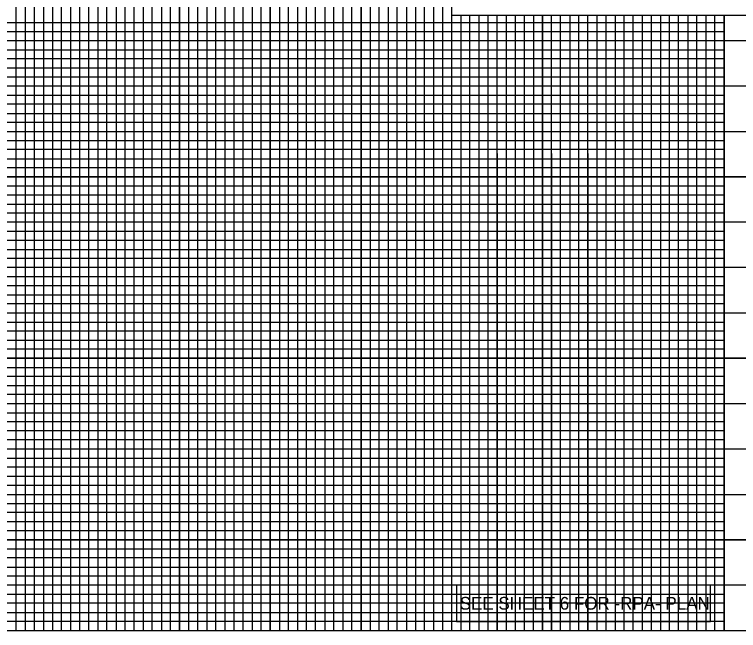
# Model space of a CAD drawing. Extents: x 1648862 to 1650715, y 820691 to 821791.
# Drawn here: x 1650088.3 to 1650487.2, y 821266 to 821605.5 of the extents above; entities that cross this region are included whole.
import ezdxf

# ---------------------------------------------------------------- set-up
doc = ezdxf.new("R2010")
doc.units = 0
for name, color, linetype in [('Prop Dimension', 7, 'Continuous'), ('Prop Grid Mask', 7, 'Continuous'), ('Sheet DOT Grid CELL', 7, 'Continuous'), ('Sheet Layout Profile Border Port 1', 7, 'Continuous'), ('Sheet Profile CELL', 7, 'Continuous'), ('Sheet Profile Grid Major CELL', 7, 'Continuous'), ('Sheet Profile Grid Middle CELL', 7, 'Continuous'), ('Sheet Profile Grid Minor CELL', 7, 'Continuous'), ('Sheet Sticker Exception Certification CELL', 7, 'Continuous')]:
    doc.layers.add(name, color=color, linetype=linetype)

msp = doc.modelspace()

# ---------------------------------------------------------------- linework, layer by layer
at = {"layer": 'Prop Grid Mask'}
msp.add_lwpolyline([(1650331.78, 821291.02), (1650331.78, 821271.02), (1650471.78, 821271.02), (1650471.78, 821291.02)], close=True, dxfattribs=at)
at = {"layer": 'Sheet DOT Grid CELL'}
for p, q in [((1650129.28, 821266.02), (1650129.28, 821718.48)), ((1650179.28, 821266.02), (1650179.28, 821716.02)), ((1650229.28, 821266.02), (1650229.28, 821718.48)), ((1650279.28, 821266.02), (1650279.28, 821718.48)), ((1650329.28, 821266.02), (1650329.28, 821628.47)), ((1650379.28, 821266.02), (1650379.28, 821604.97)), ((1650429.28, 821266.02), (1650429.28, 821604.97)), ((1650479.28, 821266.02), (1650479.28, 821604.97)), ((1650529.28, 821566.02), (1649029.28, 821566.02)), ((1650529.28, 821516.02), (1649029.28, 821516.02)), ((1650529.28, 821466.02), (1649029.28, 821466.02)), ((1650529.28, 821416.02), (1649029.28, 821416.02)), ((1650529.28, 821366.02), (1649029.28, 821366.02)), ((1650529.28, 821316.02), (1649029.28, 821316.02))]:
    msp.add_line(p, q, dxfattribs=at)
at = {"layer": 'Sheet Layout Profile Border Port 1'}
msp.add_lwpolyline([(1649079.28, 821604.97), (1649079.28, 821266.02), (1650479.28, 821266.02), (1650479.28, 821604.97)], dxfattribs=at)
at = {"layer": 'Sheet Profile CELL'}
msp.add_line((1649029.28, 821266.02), (1650529.28, 821266.02), dxfattribs=at)
at = {"layer": 'Sheet Profile Grid Major CELL'}
for points in [[(1650079.23, 821266.02), (1650129.23, 821266.02), (1650129.23, 821766.02), (1650179.23, 821766.02), (1650179.23, 821266.02), (1650229.23, 821266.02), (1650229.23, 821738.96)], [(1650279.23, 821738.96), (1650279.23, 821266.02), (1650329.23, 821266.02), (1650329.23, 821766.02), (1650355.53, 821766.02)], [(1650479.28, 821604.97), (1650479.28, 821266.02), (1650529.28, 821266.02), (1650529.28, 821616.02)], [(1650379.23, 821604.97), (1650379.23, 821266.02), (1650429.23, 821266.02), (1650429.23, 821266.02), (1650429.23, 821604.97)], [(1650529.23, 821566.02), (1649029.23, 821566.02), (1649029.23, 821516.02), (1650529.23, 821516.02)], [(1650529.23, 821466.02), (1649029.23, 821466.02), (1649029.23, 821416.02), (1650529.23, 821416.02)], [(1650529.23, 821366.02), (1649029.23, 821366.02), (1649029.23, 821366.02), (1649029.23, 821316.02), (1650529.23, 821316.02)]]:
    msp.add_lwpolyline(points, dxfattribs=at)
at = {"layer": 'Sheet Profile Grid Middle CELL'}
for points in [[(1650054.23, 821766.02), (1650104.23, 821766.02), (1650104.23, 821266.02), (1650154.23, 821266.02), (1650154.23, 821766.02), (1650204.23, 821766.02)], [(1650204.23, 821738.96), (1650204.23, 821266.02), (1650254.23, 821266.02), (1650254.23, 821738.96)], [(1650304.23, 821738.96), (1650304.23, 821266.02), (1650354.23, 821266.02), (1650354.23, 821604.97)], [(1650354.23, 821528.82), (1650354.23, 821266.02), (1650404.23, 821266.02), (1650404.23, 821604.97)], [(1650404.23, 821528.82), (1650404.23, 821266.02), (1650454.23, 821266.02), (1650454.23, 821604.97)], [(1650529.23, 821591.02), (1649029.23, 821591.02), (1649029.23, 821541.02), (1650354.23, 821541.02)], [(1650354.23, 821541.02), (1650529.23, 821541.02)], [(1650354.23, 821541.02), (1650529.23, 821541.02)], [(1650529.23, 821491.02), (1649029.23, 821491.02), (1649029.23, 821441.02), (1650529.23, 821441.02)], [(1650529.23, 821391.02), (1649029.23, 821391.02), (1649029.23, 821341.02), (1650529.23, 821341.02)], [(1650529.23, 821291.02), (1649029.23, 821291.02)]]:
    msp.add_lwpolyline(points, dxfattribs=at)
at = {"layer": 'Sheet Profile Grid Minor CELL'}
for p, q in [((1649079.23, 821601.02), (1650479.23, 821601.02)), ((1650479.23, 821581.02), (1649079.23, 821581.02)), ((1649079.23, 821576.02), (1650479.23, 821576.02)), ((1650479.23, 821556.02), (1649079.23, 821556.02)), ((1649079.23, 821551.02), (1650479.23, 821551.02)), ((1650479.23, 821531.02), (1649079.23, 821531.02)), ((1649079.23, 821526.02), (1650479.23, 821526.02)), ((1650479.23, 821521.02), (1649079.23, 821521.02)), ((1649079.23, 821511.02), (1650479.23, 821511.02)), ((1650479.23, 821506.02), (1649079.23, 821506.02)), ((1649079.23, 821501.02), (1650479.23, 821501.02)), ((1650479.23, 821496.02), (1649079.23, 821496.02)), ((1649079.23, 821486.02), (1650479.23, 821486.02)), ((1650479.23, 821481.02), (1649079.23, 821481.02)), ((1649079.23, 821476.02), (1650479.23, 821476.02)), ((1650479.23, 821471.02), (1649079.23, 821471.02)), ((1649079.23, 821461.02), (1650479.23, 821461.02)), ((1650479.23, 821456.02), (1649079.23, 821456.02)), ((1649079.23, 821451.02), (1650479.23, 821451.02)), ((1650479.23, 821446.02), (1649079.23, 821446.02)), ((1649079.23, 821436.02), (1650479.23, 821436.02)), ((1650479.23, 821431.02), (1649079.23, 821431.02)), ((1649079.23, 821426.02), (1650479.23, 821426.02)), ((1650479.23, 821421.02), (1649079.23, 821421.02)), ((1649079.23, 821411.02), (1650479.23, 821411.02)), ((1650479.23, 821406.02), (1649079.23, 821406.02)), ((1649079.23, 821401.02), (1650479.23, 821401.02)), ((1650479.23, 821396.02), (1649079.23, 821396.02)), ((1649079.23, 821386.02), (1650479.23, 821386.02)), ((1650479.23, 821381.02), (1649079.23, 821381.02)), ((1650479.23, 821376.02), (1649079.23, 821376.02)), ((1650479.23, 821371.02), (1649079.23, 821371.02)), ((1649079.23, 821361.02), (1650479.23, 821361.02)), ((1650479.23, 821356.02), (1649079.23, 821356.02)), ((1649079.23, 821351.02), (1650479.23, 821351.02)), ((1650479.23, 821346.02), (1649079.23, 821346.02)), ((1649079.23, 821336.02), (1650479.23, 821336.02)), ((1650479.23, 821331.02), (1649079.23, 821331.02)), ((1649079.23, 821326.02), (1650479.23, 821326.02)), ((1650479.23, 821321.02), (1649079.23, 821321.02)), ((1649079.23, 821311.02), (1650479.23, 821311.02)), ((1650479.23, 821306.02), (1649079.23, 821306.02)), ((1649079.23, 821301.02), (1650479.23, 821301.02)), ((1650479.23, 821296.02), (1649079.23, 821296.02)), ((1649079.23, 821286.02), (1650479.23, 821286.02)), ((1650479.23, 821281.02), (1649079.23, 821281.02)), ((1649079.23, 821276.02), (1650479.23, 821276.02)), ((1650159.23, 821266.02), (1650164.23, 821266.02))]:
    msp.add_line(p, q, dxfattribs=at)
for points in [[(1650084.23, 821266.02), (1650089.23, 821266.02), (1650089.23, 821766.02)], [(1650094.23, 821766.02), (1650094.23, 821266.02), (1650099.23, 821266.02), (1650099.23, 821766.02)], [(1650109.23, 821766.02), (1650109.23, 821266.02), (1650114.23, 821266.02), (1650114.23, 821766.02)], [(1650119.23, 821766.02), (1650119.23, 821266.02), (1650124.23, 821266.02), (1650124.23, 821766.02)], [(1650134.23, 821766.02), (1650134.23, 821266.02), (1650139.23, 821266.02), (1650139.23, 821766.02)], [(1650144.23, 821766.02), (1650144.23, 821266.02), (1650149.23, 821266.02), (1650149.23, 821766.02)], [(1650159.23, 821766.02), (1650159.23, 821266.02), (1650164.23, 821266.02), (1650164.23, 821766.02)], [(1650169.23, 821766.02), (1650169.23, 821266.02), (1650174.23, 821266.02), (1650174.23, 821766.02)], [(1650184.23, 821738.96), (1650184.23, 821266.02), (1650189.23, 821266.02), (1650189.23, 821738.96)], [(1650194.23, 821738.96), (1650194.23, 821266.02), (1650199.23, 821266.02), (1650199.23, 821738.96)], [(1650209.23, 821738.96), (1650209.23, 821266.02), (1650214.23, 821266.02), (1650214.23, 821738.96)], [(1650219.23, 821266.02), (1650224.23, 821266.02), (1650224.23, 821738.96)], [(1650219.23, 821738.96), (1650219.23, 821266.02)], [(1650234.23, 821738.96), (1650234.23, 821266.02), (1650239.23, 821266.02), (1650239.23, 821738.96)], [(1650244.23, 821738.96), (1650244.23, 821266.02), (1650249.23, 821266.02), (1650249.23, 821738.96)], [(1650259.23, 821738.96), (1650259.23, 821266.02), (1650264.23, 821266.02), (1650264.23, 821738.96)], [(1650269.23, 821738.96), (1650269.23, 821266.02), (1650274.23, 821266.02), (1650274.23, 821738.96)], [(1650284.23, 821738.96), (1650284.23, 821266.02), (1650289.23, 821266.02), (1650289.23, 821738.96)], [(1650294.23, 821738.96), (1650294.23, 821266.02), (1650299.23, 821266.02), (1650299.23, 821738.96)], [(1650309.23, 821738.96), (1650309.23, 821266.02), (1650314.23, 821266.02), (1650314.23, 821738.96)], [(1650319.23, 821738.96), (1650319.23, 821266.02), (1650324.23, 821266.02), (1650324.23, 821738.96)], [(1650334.23, 821604.97), (1650334.23, 821266.02), (1650339.23, 821266.02), (1650339.23, 821604.97)], [(1650344.23, 821604.97), (1650344.23, 821266.02), (1650349.23, 821266.02), (1650349.23, 821604.97)], [(1650359.23, 821604.97), (1650359.23, 821266.02), (1650359.23, 821266.02), (1650364.23, 821266.02), (1650369.23, 821266.02), (1650369.23, 821604.97)], [(1650364.23, 821604.97), (1650364.23, 821266.02)], [(1650374.23, 821604.97), (1650374.13, 821266.07), (1650379.13, 821266.07), (1650384.23, 821266.02), (1650384.23, 821604.97)], [(1650384.23, 821528.82), (1650384.23, 821266.02), (1650389.23, 821266.02), (1650389.23, 821604.97)], [(1650394.23, 821604.97), (1650394.23, 821266.02), (1650399.23, 821266.02), (1650399.23, 821604.97)], [(1650409.23, 821604.97), (1650409.23, 821266.02), (1650414.23, 821266.02), (1650414.23, 821604.97)], [(1650419.23, 821604.97), (1650419.23, 821266.02), (1650424.23, 821266.02), (1650424.23, 821604.97)], [(1650434.23, 821604.97), (1650434.23, 821266.02), (1650439.23, 821266.02), (1650439.23, 821604.97)], [(1650444.23, 821604.97), (1650444.23, 821266.02), (1650449.23, 821266.02), (1650449.23, 821604.97)], [(1650459.23, 821604.97), (1650459.23, 821266.02), (1650464.23, 821266.02), (1650464.23, 821604.97)], [(1650469.23, 821604.97), (1650469.23, 821266.02), (1650474.23, 821266.02), (1650474.23, 821604.97)], [(1650479.23, 821596.02), (1649079.23, 821596.02), (1649079.23, 821586.02), (1650479.23, 821586.02)], [(1650479.23, 821571.02), (1649079.23, 821571.02), (1649079.23, 821561.02), (1650479.23, 821561.02)], [(1650479.23, 821546.02), (1649079.23, 821546.02), (1649079.23, 821536.02), (1650479.23, 821536.02)], [(1650479.23, 821271.02), (1649079.23, 821271.02)]]:
    msp.add_lwpolyline(points, dxfattribs=at)
at = {"layer": 'Sheet Sticker Exception Certification CELL'}
for p, q in [((1650329.23, 821604.97), (1650329.23, 821628.47)), ((1650329.23, 821604.97), (1650329.23, 821628.47)), ((1650529.27, 821604.97), (1650329.23, 821604.97)), ((1650529.27, 821604.97), (1650329.23, 821604.97))]:
    msp.add_line(p, q, dxfattribs=at)

# ---------------------------------------------------------------- texts
at = {"layer": 'Prop Dimension'}
msp.add_text('SEE SHEET 6 FOR -RPA- PLAN', height=7, dxfattribs=at).set_placement((1650333.58, 821277.52))

doc.saveas('drawing.dxf')
